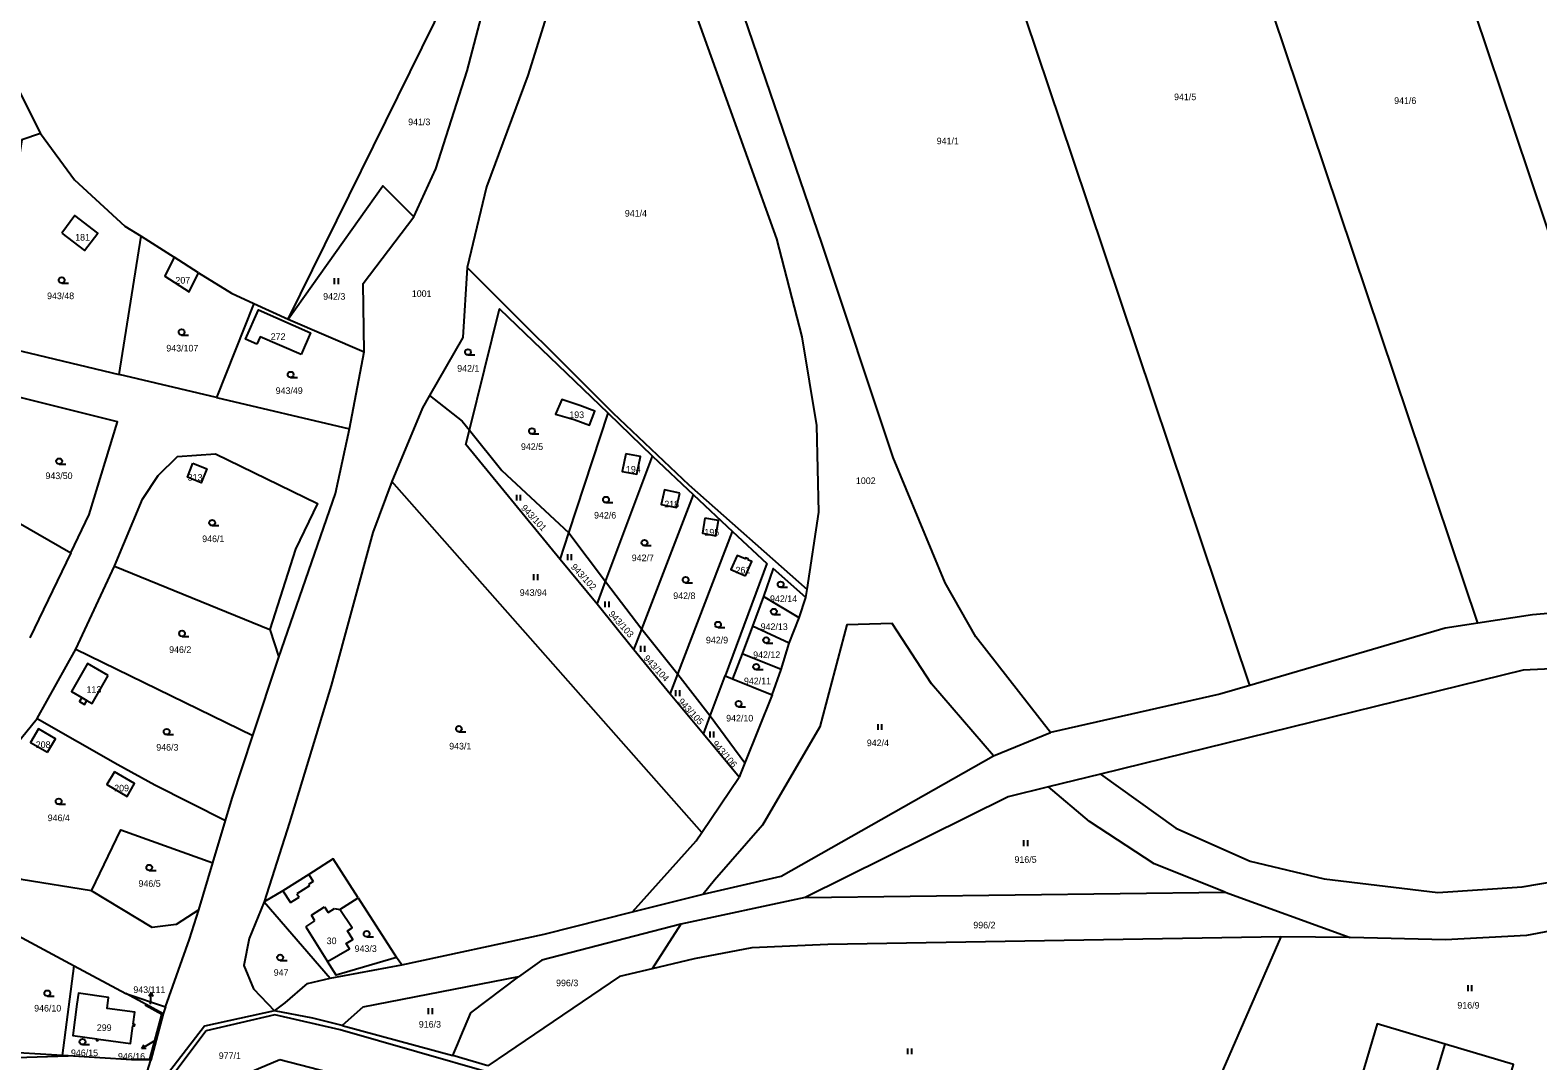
# Model space of a CAD drawing. Extents: x -7476540 to -746055, y -11317203 to -1129777.
# Drawn here: x -750645.6 to -750258.6, y -1131231.7 to -1130967.2 of the extents above; entities that cross this region are included whole.
import ezdxf

# ---------------------------------------------------------------- set-up
doc = ezdxf.new("R2010")
doc.units = 0
for name, color, linetype in [('Hranice parcel', 7, 'Continuous'), ('Parcelní čísla', 7, 'Continuous'), ('Pop  PČ popisy', 7, 'Continuous'), ('Vnitřní kresba', 7, 'Continuous'), ('Značky kultur', 7, 'Continuous')]:
    doc.layers.add(name, color=color, linetype=linetype)

msp = doc.modelspace()

# ---------------------------------------------------------------- linework, layer by layer
at = {"layer": 'Hranice parcel'}
for p, q in [((-750653.79, -1130972.43), (-750642.94, -1130993.73)), ((-750622.78, -1131055.54), (-750617.17, -1131020.08)), ((-750617.17, -1131020.08), (-750608.62, -1131025.49)), ((-750602.38, -1131029.51), (-750608.62, -1131025.49)), ((-750588.24, -1131037.32), (-750597.78, -1131061.49)), ((-750588.24, -1131037.32), (-750579.43, -1131041.4)), ((-750579.43, -1131041.4), (-750559.85, -1131049.76)), ((-750563.69, -1131069.55), (-750559.85, -1131049.76)), ((-750597.78, -1131061.49), (-750622.78, -1131055.54)), ((-750597.78, -1131061.49), (-750563.69, -1131069.55)), ((-750507.32, -1131096.22), (-750497.27, -1131065.52)), ((-750497.27, -1131065.52), (-750485.87, -1131076.56)), ((-750497.91, -1131108.74), (-750485.87, -1131076.56)), ((-750485.87, -1131076.56), (-750475.37, -1131086.44)), ((-750473.19, -1131173.15), (-750552.77, -1131083.07)), ((-750658.73, -1131087.82), (-750635.2, -1131101.36)), ((-750488.61, -1131120.96), (-750475.37, -1131086.44)), ((-750475.37, -1131086.44), (-750465.29, -1131095.85)), ((-750509.57, -1131103.09), (-750507.32, -1131096.22)), ((-750507.32, -1131096.22), (-750497.91, -1131108.74)), ((-750479.38, -1131132.47), (-750465.29, -1131095.85)), ((-750635.2, -1131101.36), (-750645.75, -1131123.19)), ((-750633.92, -1131126.08), (-750623.98, -1131104.75)), ((-750623.98, -1131104.75), (-750584.08, -1131121.02)), ((-750500.08, -1131114.54), (-750509.57, -1131103.09)), ((-750500.08, -1131114.54), (-750497.91, -1131108.74)), ((-750497.91, -1131108.74), (-750488.61, -1131120.96)), ((-750457.41, -1131112.56), (-750460.24, -1131120.18)), ((-750448.23, -1131118.01), (-750457.41, -1131112.56)), ((-750446.53, -1131112.81), (-750446.13, -1131110.72)), ((-750490.63, -1131126.23), (-750500.08, -1131114.54)), ((-750448.23, -1131118.01), (-750446.53, -1131112.81)), ((-750460.24, -1131120.18), (-750462.82, -1131127.24)), ((-750450.77, -1131124.56), (-750460.24, -1131120.18)), ((-750450.77, -1131124.56), (-750448.23, -1131118.01)), ((-750584.08, -1131121.02), (-750581.77, -1131128.11)), ((-750490.63, -1131126.23), (-750488.61, -1131120.96)), ((-750488.61, -1131120.96), (-750479.38, -1131132.47)), ((-750643.85, -1131143.83), (-750633.92, -1131126.08)), ((-750633.92, -1131126.08), (-750588.48, -1131148.2)), ((-750588.48, -1131148.2), (-750581.77, -1131128.11)), ((-750481.37, -1131137.63), (-750490.63, -1131126.23)), ((-750462.82, -1131127.24), (-750465.37, -1131133.64)), ((-750452.87, -1131131.28), (-750462.82, -1131127.24)), ((-750452.87, -1131131.28), (-750450.77, -1131124.56)), ((-750455.14, -1131137.79), (-750452.87, -1131131.28)), ((-750481.37, -1131137.63), (-750479.38, -1131132.47)), ((-750479.38, -1131132.47), (-750471.07, -1131143.22)), ((-750471.07, -1131143.22), (-750467.23, -1131132.9)), ((-750467.23, -1131132.9), (-750465.37, -1131133.64)), ((-750465.37, -1131133.64), (-750455.14, -1131137.79)), ((-750472.81, -1131147.91), (-750481.37, -1131137.63)), ((-750455.14, -1131137.79), (-750462.15, -1131155.21)), ((-750472.81, -1131147.91), (-750471.07, -1131143.22)), ((-750471.07, -1131143.22), (-750462.15, -1131155.21)), ((-750398.36, -1131153.41), (-750383.69, -1131147.48)), ((-750463.62, -1131158.93), (-750472.81, -1131147.91)), ((-750473.19, -1131173.15), (-750463.62, -1131158.93)), ((-750370.85, -1131158.14), (-750384.23, -1131161.42)), ((-750598.74, -1131180.95), (-750595.5, -1131170.04)), ((-750602.36, -1131193.01), (-750598.74, -1131180.95)), ((-750580.75, -1131188.08), (-750585.52, -1131190.95)), ((-750566.12, -1131192.88), (-750561.42, -1131189.86)), ((-750561.42, -1131189.86), (-750551.57, -1131205.21)), ((-750491, -1131193.51), (-750472.83, -1131188.97)), ((-750446.64, -1131189.81), (-750478.58, -1131196.61)), ((-750446.64, -1131189.81), (-750338.88, -1131188.45)), ((-750338.88, -1131188.45), (-750306.79, -1131200.03)), ((-750663.9, -1131191.45), (-750634.31, -1131207.35)), ((-750585.52, -1131190.95), (-750568.64, -1131210.54)), ((-750478.58, -1131196.61), (-750485.93, -1131208.1)), ((-750324.56, -1131199.94), (-750360.45, -1131282.22)), ((-750306.79, -1131200.03), (-750324.56, -1131199.94)), ((-750550.24, -1131207.13), (-750551.57, -1131205.21)), ((-750637.34, -1131230.32), (-750634.31, -1131207.35)), ((-750634.31, -1131207.35), (-750621.05, -1131214.47)), ((-750568.64, -1131210.54), (-750550.24, -1131207.13)), ((-750615.88, -1131217.25), (-750621.05, -1131214.47)), ((-750621.05, -1131214.47), (-750610.86, -1131217.83)), ((-750611.5, -1131219.65), (-750615.88, -1131217.25)), ((-750611.5, -1131219.65), (-750614.64, -1131231.58)), ((-750610.86, -1131217.83), (-750611.5, -1131219.65)), ((-750565.51, -1131222.62), (-750537.12, -1131230.36)), ((-750637.34, -1131230.32), (-750676.72, -1131228.08)), ((-750292.72, -1131262.14), (-750282.4, -1131227.41)), ((-750635.87, -1131230.45), (-750637.34, -1131230.32)), ((-750619.64, -1131231.48), (-750635.87, -1131230.45)), ((-750614.64, -1131231.58), (-750619.64, -1131231.48)), ((-750617.63, -1131241.09), (-750614.64, -1131231.58)), ((-750528.14, -1131233.04), (-750537.12, -1131230.36))]:
    msp.add_line(p, q, dxfattribs=at)
for points in [[(-750332.51, -1131135.35), (-750377.98, -1131000.04), (-750423.45, -1130864.72)], [(-750274.04, -1131119.43), (-750316.73, -1130992.37), (-750359.42, -1130865.31)], [(-750223.88, -1131114.14), (-750264.62, -1130992.88), (-750305.36, -1130871.62)], [(-750383.69, -1131147.48), (-750402.83, -1131122.9), (-750410.73, -1131109.04), (-750424.07, -1131076.84), (-750442.36, -1131021.87), (-750466.73, -1130950.73), (-750487.24, -1130888.84), (-750489.98, -1130882.7)], [(-750579.43, -1131041.4), (-750541.82, -1130965.24), (-750511.43, -1130902.47)], [(-750547.16, -1131015.06), (-750541.48, -1131002.77), (-750533.47, -1130977.66), (-750525.19, -1130946.2), (-750513.6, -1130914.64), (-750511.43, -1130902.47)], [(-750495.43, -1130900.48), (-750502.66, -1130930.1), (-750517.9, -1130978.8), (-750528.5, -1131007.43), (-750533.48, -1131028.12)], [(-750446.13, -1131110.72), (-750443.13, -1131090.87), (-750443.7, -1131068.64), (-750447.41, -1131045.86), (-750453.97, -1131020.75), (-750476.26, -1130958.59), (-750488.96, -1130919.57), (-750495.43, -1130900.48)], [(-750642.94, -1130993.73), (-750647.77, -1130995.31), (-750656.09, -1131047.61), (-750622.78, -1131055.54)], [(-750642.94, -1130993.73), (-750634.22, -1131005.62), (-750621.28, -1131017.48), (-750617.17, -1131020.08)], [(-750579.43, -1131041.4), (-750555.12, -1131007.18), (-750547.16, -1131015.06)], [(-750637.46, -1131019.3), (-750631.68, -1131023.76), (-750628.24, -1131019.3), (-750634.13, -1131014.8), (-750637.46, -1131019.3)], [(-750559.85, -1131049.76), (-750560.14, -1131032.23), (-750547.16, -1131015.06)], [(-750608.62, -1131025.49), (-750611.05, -1131030.29), (-750604.82, -1131034.31), (-750602.38, -1131029.51)], [(-750602.38, -1131029.51), (-750593.96, -1131034.68), (-750588.24, -1131037.32)], [(-750533.48, -1131028.12), (-750534.57, -1131046.11), (-750543.09, -1131060.97)], [(-750533.48, -1131028.12), (-750496.07, -1131065.4), (-750476.55, -1131083.89), (-750446.13, -1131110.72)], [(-750587.42, -1131047.77), (-750590.31, -1131046.51), (-750587.05, -1131039), (-750573.69, -1131044.84), (-750576.08, -1131050.47)], [(-750532.86, -1131069.86), (-750525.13, -1131038.7), (-750497.27, -1131065.52)], [(-750576.08, -1131050.47), (-750586.62, -1131045.94), (-750587.42, -1131047.77)], [(-750635.2, -1131101.36), (-750630.48, -1131091.47), (-750623.21, -1131067.69), (-750651.64, -1131060.63)], [(-750543.09, -1131060.97), (-750544.92, -1131064.15), (-750552.77, -1131083.07)], [(-750543.09, -1131060.97), (-750534.76, -1131067.51), (-750532.86, -1131069.86)], [(-750504.56, -1131063.49), (-750509.16, -1131062.02), (-750510.79, -1131065.79), (-750506.01, -1131067.14), (-750502.06, -1131068.59), (-750500.68, -1131064.97), (-750504.56, -1131063.49)], [(-750581.77, -1131128.11), (-750567.23, -1131086.09), (-750563.69, -1131069.55)], [(-750509.57, -1131103.09), (-750533.78, -1131073.55), (-750532.86, -1131069.86)], [(-750532.86, -1131069.86), (-750524.54, -1131080.18), (-750507.32, -1131096.22)], [(-750623.98, -1131104.75), (-750616.75, -1131087.54), (-750612.73, -1131081.49), (-750607.8, -1131076.65), (-750598.04, -1131075.93), (-750571.89, -1131088.67), (-750577.49, -1131100.38), (-750584.08, -1131121.02)], [(-750492.72, -1131075.93), (-750493.64, -1131080.46), (-750489.87, -1131081.14), (-750488.93, -1131076.61), (-750492.72, -1131075.93)], [(-750603.83, -1131078.3), (-750600.26, -1131079.81), (-750601.72, -1131083.35), (-750605.26, -1131081.88), (-750603.83, -1131078.3)], [(-750552.77, -1131083.07), (-750557.65, -1131096.13), (-750568.36, -1131135.43), (-750579.01, -1131170.54), (-750585.52, -1131190.95)], [(-750478.89, -1131086.02), (-750482.83, -1131085.21), (-750483.68, -1131088.93), (-750479.74, -1131089.74), (-750478.89, -1131086.02)], [(-750472.41, -1131092.46), (-750473.07, -1131096.33), (-750469.61, -1131096.96), (-750468.91, -1131093.02), (-750472.41, -1131092.46)], [(-750465.29, -1131095.85), (-750456.53, -1131104.12), (-750467.23, -1131132.9)], [(-750461.4, -1131103.14), (-750461.28, -1131102.87), (-750461.99, -1131102.61), (-750462.09, -1131102.85), (-750464.13, -1131101.99), (-750465.72, -1131105.65), (-750461.99, -1131107.27)], [(-750461.99, -1131107.27), (-750460.34, -1131103.59), (-750461.4, -1131103.14)], [(-750446.53, -1131112.81), (-750454.86, -1131105.37), (-750457.41, -1131112.56)], [(-750223.88, -1131114.14), (-750259.94, -1131117.26), (-750274.04, -1131119.43)], [(-750398.36, -1131153.41), (-750414.23, -1131134.96), (-750424.36, -1131119.49), (-750435.97, -1131119.86), (-750442.91, -1131145.97), (-750457.63, -1131171.27), (-750469.94, -1131185.39), (-750472.83, -1131188.97)], [(-750370.85, -1131158.14), (-750351.54, -1131171.98), (-750332.45, -1131180.52), (-750313.48, -1131185.03), (-750284.31, -1131188.5), (-750262.6, -1131187.08), (-750237.96, -1131182.86), (-750198.96, -1131174.77), (-750007.37, -1131119.02)], [(-750007.37, -1131119.02), (-750096.89, -1131123.78), (-750262.33, -1131131.47), (-750370.85, -1131158.14)], [(-750274.04, -1131119.43), (-750282.4, -1131120.71), (-750332.51, -1131135.35)], [(-750625.57, -1131132.81), (-750630.88, -1131129.76), (-750635.02, -1131136.97), (-750632.39, -1131138.48), (-750632.98, -1131139.52), (-750631.64, -1131140.29), (-750631.05, -1131139.25), (-750629.72, -1131140.04), (-750625.57, -1131132.81)], [(-750332.51, -1131135.35), (-750340.2, -1131137.6), (-750383.69, -1131147.48)], [(-750629.89, -1131188.07), (-750647.96, -1131185.17), (-750660.39, -1131170.67), (-750661.43, -1131165.52), (-750643.85, -1131143.83)], [(-750641.17, -1131152.51), (-750639.14, -1131149.06), (-750643.44, -1131146.53), (-750645.5, -1131150.03), (-750641.17, -1131152.51)], [(-750643.85, -1131143.83), (-750623.08, -1131155.63), (-750613.63, -1131160.87), (-750595.5, -1131170.04)], [(-750595.5, -1131170.04), (-750593.76, -1131164.33), (-750588.48, -1131148.2)], [(-750472.83, -1131188.97), (-750452.8, -1131184.37), (-750398.36, -1131153.41)], [(-750462.15, -1131155.21), (-750463.19, -1131157.85), (-750463.62, -1131158.93)], [(-750624.01, -1131157.51), (-750625.92, -1131160.82), (-750620.73, -1131163.85), (-750618.82, -1131160.58), (-750624.01, -1131157.51)], [(-750384.23, -1131161.42), (-750394.55, -1131163.95), (-750446.64, -1131189.81)], [(-750338.88, -1131188.45), (-750357.11, -1131181.19), (-750373.67, -1131170.27), (-750384.23, -1131161.42)], [(-750629.89, -1131188.07), (-750622.31, -1131172.46), (-750598.74, -1131180.95)], [(-750491, -1131193.51), (-750474.63, -1131175.29), (-750473.19, -1131173.15)], [(-750561.42, -1131189.86), (-750567.81, -1131179.9), (-750574.13, -1131183.9), (-750580.75, -1131188.08)], [(-750602.36, -1131193.01), (-750608.11, -1131196.71), (-750614.32, -1131197.54), (-750629.89, -1131188.07)], [(-750213.06, -1131188.66), (-750241.04, -1131195.74), (-750261.52, -1131199.54), (-750282.31, -1131200.69), (-750306.79, -1131200.03)], [(-750610.86, -1131217.83), (-750604.75, -1131200.5), (-750602.36, -1131193.01)], [(-750585.52, -1131190.95), (-750589.37, -1131200.29), (-750590.81, -1131207.27), (-750588.28, -1131213.22), (-750582.93, -1131218.86)], [(-750551.57, -1131205.21), (-750567.07, -1131209.71), (-750569.3, -1131206.19), (-750563.67, -1131202.94), (-750564.53, -1131201.59), (-750562.76, -1131200.55), (-750564.16, -1131198.33), (-750562.99, -1131197.56), (-750566.12, -1131192.88)], [(-750550.24, -1131207.13), (-750513.65, -1131199.22), (-750491, -1131193.51)], [(-750478.58, -1131196.61), (-750514.29, -1131205.87), (-750520.23, -1131210.17)], [(-750324.56, -1131199.94), (-750440.85, -1131201.86), (-750460.37, -1131202.74), (-750475.17, -1131205.54), (-750485.93, -1131208.1)], [(-750485.93, -1131208.1), (-750494.34, -1131210.1), (-750520.95, -1131228.16), (-750523.07, -1131229.6), (-750528.14, -1131233.04)], [(-750582.93, -1131218.86), (-750580.15, -1131216.88), (-750574.41, -1131211.88), (-750568.64, -1131210.54)], [(-750520.23, -1131210.17), (-750560.2, -1131217.92), (-750565.51, -1131222.62)], [(-750537.12, -1131230.36), (-750535.86, -1131227.39), (-750535.03, -1131225.44), (-750532.48, -1131219.42), (-750520.23, -1131210.17)], [(-750628.17, -1131226.54), (-750628.11, -1131226.14), (-750619.86, -1131227.28), (-750619.23, -1131222.73), (-750618.83, -1131222.78), (-750618.78, -1131222.38), (-750619.17, -1131222.33), (-750618.75, -1131219.27), (-750625.88, -1131218.29), (-750625.49, -1131215.43), (-750633.21, -1131214.37), (-750633.6, -1131217.22), (-750634.7, -1131225.23), (-750628.5, -1131226.09), (-750628.56, -1131226.48), (-750628.17, -1131226.54)], [(-750619.64, -1131231.48), (-750619.63, -1131231.18), (-750614.87, -1131231.27), (-750611.85, -1131219.8), (-750616.03, -1131217.51), (-750615.88, -1131217.25)], [(-750582.93, -1131218.86), (-750600.91, -1131222.79), (-750618.46, -1131245.66)], [(-750565.51, -1131222.62), (-750573.02, -1131220.81), (-750582.93, -1131218.86)], [(-750818.16, -1131224.81), (-750709.78, -1131231), (-750659.74, -1131231.2), (-750635.87, -1131230.45)], [(-750282.4, -1131227.41), (-750299.84, -1131222.2), (-750310.14, -1131256.86)], [(-750275.17, -1131267.37), (-750264.83, -1131232.64), (-750282.4, -1131227.41)]]:
    msp.add_lwpolyline(points, dxfattribs=at)
at = {"layer": 'Pop  PČ popisy'}
for p, q in [((-750614.58, -1131214.2), (-750615.14, -1131215.18)), ((-750614.74, -1131217.2), (-750614.58, -1131214.2)), ((-750614.58, -1131214.2), (-750614.14, -1131215.23)), ((-750614.38, -1131227.04), (-750616.98, -1131228.54)), ((-750616.98, -1131228.54), (-750616.36, -1131227.61)), ((-750616.98, -1131228.54), (-750615.86, -1131228.47)), ((-750613.36, -1131226.46), (-750614.38, -1131227.04))]:
    msp.add_line(p, q, dxfattribs=at)
at = {"layer": 'Vnitřní kresba'}
for p, q in [((-750632.39, -1131138.48), (-750631.05, -1131139.25)), ((-750573.01, -1131185.68), (-750574.2, -1131186.43)), ((-750574.13, -1131183.9), (-750573.01, -1131185.68)), ((-750580.75, -1131188.08), (-750578.82, -1131191.13)), ((-750578.82, -1131191.13), (-750576.61, -1131189.74)), ((-750573.93, -1131186.85), (-750577.15, -1131188.89)), ((-750577.15, -1131188.89), (-750576.61, -1131189.74)), ((-750574.2, -1131186.43), (-750573.93, -1131186.85)), ((-750573.44, -1131194.38), (-750570.05, -1131192.24)), ((-750570.05, -1131192.24), (-750569.14, -1131193.68)), ((-750569.14, -1131193.68), (-750567.53, -1131192.65)), ((-750567.53, -1131192.65), (-750566.12, -1131192.88)), ((-750574.9, -1131197.33), (-750572.53, -1131195.82)), ((-750574.9, -1131197.33), (-750569.3, -1131206.19)), ((-750572.53, -1131195.82), (-750573.44, -1131194.38)), ((-750582.84, -1131219.92), (-750600.48, -1131224.07)), ((-750566.04, -1131223.81), (-750582.84, -1131219.92)), ((-750600.48, -1131224.07), (-750617.99, -1131247.26)), ((-750506.88, -1131240.71), (-750566.04, -1131223.81)), ((-750581.51, -1131231.45), (-750591.91, -1131235.86)), ((-750553.71, -1131238.62), (-750581.51, -1131231.45))]:
    msp.add_line(p, q, dxfattribs=at)
at = {"layer": 'Značky kultur'}
for p, q in [((-750567.48, -1131032.38), (-750567.48, -1131030.88)), ((-750566.48, -1131032.38), (-750566.48, -1131030.88)), ((-750637.53, -1131032.11), (-750635.78, -1131032.11)), ((-750606.74, -1131045.43), (-750604.99, -1131045.43)), ((-750533.24, -1131050.56), (-750531.49, -1131050.56)), ((-750578.76, -1131056.35), (-750577.01, -1131056.35)), ((-750516.81, -1131070.83), (-750515.06, -1131070.83)), ((-750638.2, -1131078.59), (-750636.45, -1131078.59)), ((-750520.73, -1131087.95), (-750520.73, -1131086.45)), ((-750519.73, -1131087.95), (-750519.73, -1131086.45)), ((-750497.81, -1131088.44), (-750496.06, -1131088.44)), ((-750598.9, -1131094.36), (-750597.15, -1131094.36)), ((-750487.94, -1131099.49), (-750486.19, -1131099.49)), ((-750507.64, -1131103.22), (-750507.64, -1131101.72)), ((-750506.64, -1131103.22), (-750506.64, -1131101.72)), ((-750516.34, -1131108.35), (-750516.34, -1131106.85)), ((-750515.34, -1131108.35), (-750515.34, -1131106.85)), ((-750477.36, -1131109.02), (-750475.61, -1131109.02)), ((-750452.97, -1131110.19), (-750451.22, -1131110.19)), ((-750498, -1131115.31), (-750498, -1131113.81)), ((-750497, -1131115.31), (-750497, -1131113.81)), ((-750454.73, -1131117.19), (-750452.98, -1131117.19)), ((-750606.63, -1131122.79), (-750604.88, -1131122.79)), ((-750469.04, -1131120.52), (-750467.29, -1131120.52)), ((-750488.87, -1131126.72), (-750488.87, -1131125.22)), ((-750487.87, -1131126.72), (-750487.87, -1131125.22)), ((-750456.69, -1131124.51), (-750454.94, -1131124.51)), ((-750459.24, -1131131.32), (-750457.49, -1131131.32)), ((-750479.89, -1131138.1), (-750479.89, -1131136.6)), ((-750478.89, -1131138.1), (-750478.89, -1131136.6)), ((-750463.76, -1131140.83), (-750462.01, -1131140.83)), ((-750535.56, -1131147.27), (-750533.81, -1131147.27)), ((-750471.09, -1131148.71), (-750471.09, -1131147.21)), ((-750470.09, -1131148.71), (-750470.09, -1131147.21)), ((-750427.96, -1131146.79), (-750427.96, -1131145.29)), ((-750426.96, -1131146.79), (-750426.96, -1131145.29)), ((-750610.58, -1131148.01), (-750608.83, -1131148.01)), ((-750638.3, -1131165.89), (-750636.55, -1131165.89)), ((-750390.56, -1131176.61), (-750390.56, -1131175.11)), ((-750389.56, -1131176.61), (-750389.56, -1131175.11)), ((-750615.05, -1131182.89), (-750613.3, -1131182.89)), ((-750559.24, -1131199.89), (-750557.49, -1131199.89)), ((-750581.44, -1131205.97), (-750579.69, -1131205.97)), ((-750276.51, -1131213.81), (-750276.51, -1131212.31)), ((-750275.51, -1131213.81), (-750275.51, -1131212.31)), ((-750641.21, -1131215.14), (-750639.46, -1131215.14)), ((-750543.36, -1131219.73), (-750543.36, -1131218.23)), ((-750542.36, -1131219.73), (-750542.36, -1131218.23)), ((-750632.18, -1131227.57), (-750630.43, -1131227.57)), ((-750420.33, -1131230.02), (-750420.33, -1131228.52)), ((-750419.33, -1131230.02), (-750419.33, -1131228.52))]:
    msp.add_line(p, q, dxfattribs=at)
for centre in [(-750637.53, -1131031.36), (-750606.74, -1131044.68), (-750533.24, -1131049.81), (-750578.76, -1131055.6), (-750516.81, -1131070.08), (-750638.2, -1131077.84), (-750497.81, -1131087.69), (-750598.9, -1131093.61), (-750487.94, -1131098.74), (-750477.36, -1131108.27), (-750452.97, -1131109.44), (-750454.73, -1131116.44), (-750469.04, -1131119.77), (-750606.63, -1131122.04), (-750456.69, -1131123.76), (-750459.24, -1131130.57), (-750463.76, -1131140.08), (-750610.58, -1131147.26), (-750535.56, -1131146.52), (-750638.3, -1131165.14), (-750615.05, -1131182.14), (-750559.24, -1131199.14), (-750581.44, -1131205.22), (-750641.21, -1131214.39), (-750632.18, -1131226.82)]:
    msp.add_circle(centre, 0.75, dxfattribs=at)

# ---------------------------------------------------------------- texts
at = {"layer": 'Parcelní čísla'}
for s, p in [('941/5', (-750351.98, -1130985.16)), ('941/6', (-750295.49, -1130986.12)), ('941/3', (-750548.59, -1130991.58)), ('941/1', (-750412.91, -1130996.47)), ('941/4', (-750492.97, -1131015.06)), ('181', (-750634.07, -1131021.19)), ('207', (-750608.33, -1131032.23)), ('943/48', (-750641.28, -1131036.23)), ('942/3', (-750570.41, -1131036.38)), ('1001', (-750547.65, -1131035.67)), ('272', (-750583.87, -1131046.69)), ('943/107', (-750610.67, -1131049.66)), ('942/1', (-750536, -1131054.85)), ('943/49', (-750582.6, -1131060.57)), ('193', (-750507.22, -1131066.76)), ('942/5', (-750519.64, -1131074.94)), ('943/50', (-750641.69, -1131082.41)), ('313', (-750605.18, -1131082.83)), ('194', (-750492.68, -1131080.75)), ('1002', (-750433.65, -1131083.69)), ('218', (-750482.83, -1131089.69)), ('942/6', (-750500.87, -1131092.54)), ('946/1', (-750601.46, -1131098.59)), ('195', (-750472.54, -1131096.9)), ('942/7', (-750491.2, -1131103.48)), ('261', (-750464.56, -1131106.64)), ('943/94', (-750519.95, -1131112.39)), ('942/8', (-750480.54, -1131113.21)), ('942/14', (-750455.7, -1131113.97)), ('942/13', (-750458.1, -1131121.15)), ('942/9', (-750472.15, -1131124.59)), ('946/2', (-750609.95, -1131127.03)), ('942/12', (-750460.03, -1131128.36)), ('113', (-750631.15, -1131137.27)), ('942/11', (-750462.4, -1131135.09)), ('942/10', (-750466.96, -1131144.63)), ('208', (-750644.19, -1131151.43)), ('946/3', (-750613.25, -1131152.11)), ('943/1', (-750538.06, -1131151.81)), ('942/4', (-750430.85, -1131150.96)), ('209', (-750624.05, -1131162.58)), ('946/4', (-750641.12, -1131170.21)), ('916/5', (-750392.95, -1131180.91)), ('946/5', (-750617.81, -1131187.06)), ('996/2', (-750403.51, -1131197.74)), ('30', (-750569.5, -1131201.78)), ('943/3', (-750562.33, -1131203.77)), ('947', (-750583.1, -1131209.91)), ('943/111', (-750619.13, -1131214.31)), ('996/3', (-750510.62, -1131212.58)), ('916/9', (-750279.26, -1131218.32)), ('946/10', (-750644.6, -1131219.07)), ('299', (-750628.51, -1131224.06)), ('916/3', (-750545.86, -1131223.2)), ('946/15', (-750635.15, -1131230.52)), ('946/16', (-750623.08, -1131231.44)), ('977/1', (-750597.21, -1131231.25))]:
    msp.add_text(s, height=1.7, dxfattribs=at).set_placement(p)
for s, rotation, p in [('943/101', 313, (-750519.74, -1131089.93)), ('943/102', 313, (-750506.94, -1131105.09)), ('943/103', 312, (-750497.27, -1131117.16)), ('943/104', 313, (-750488.3, -1131128.54)), ('943/105', 313, (-750479.44, -1131139.64)), ('943/106', 311, (-750470.69, -1131150.44))]:
    msp.add_text(s, height=1.7, rotation=rotation, dxfattribs=at).set_placement(p)

doc.saveas('drawing.dxf')
